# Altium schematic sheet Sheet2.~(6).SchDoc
size A4
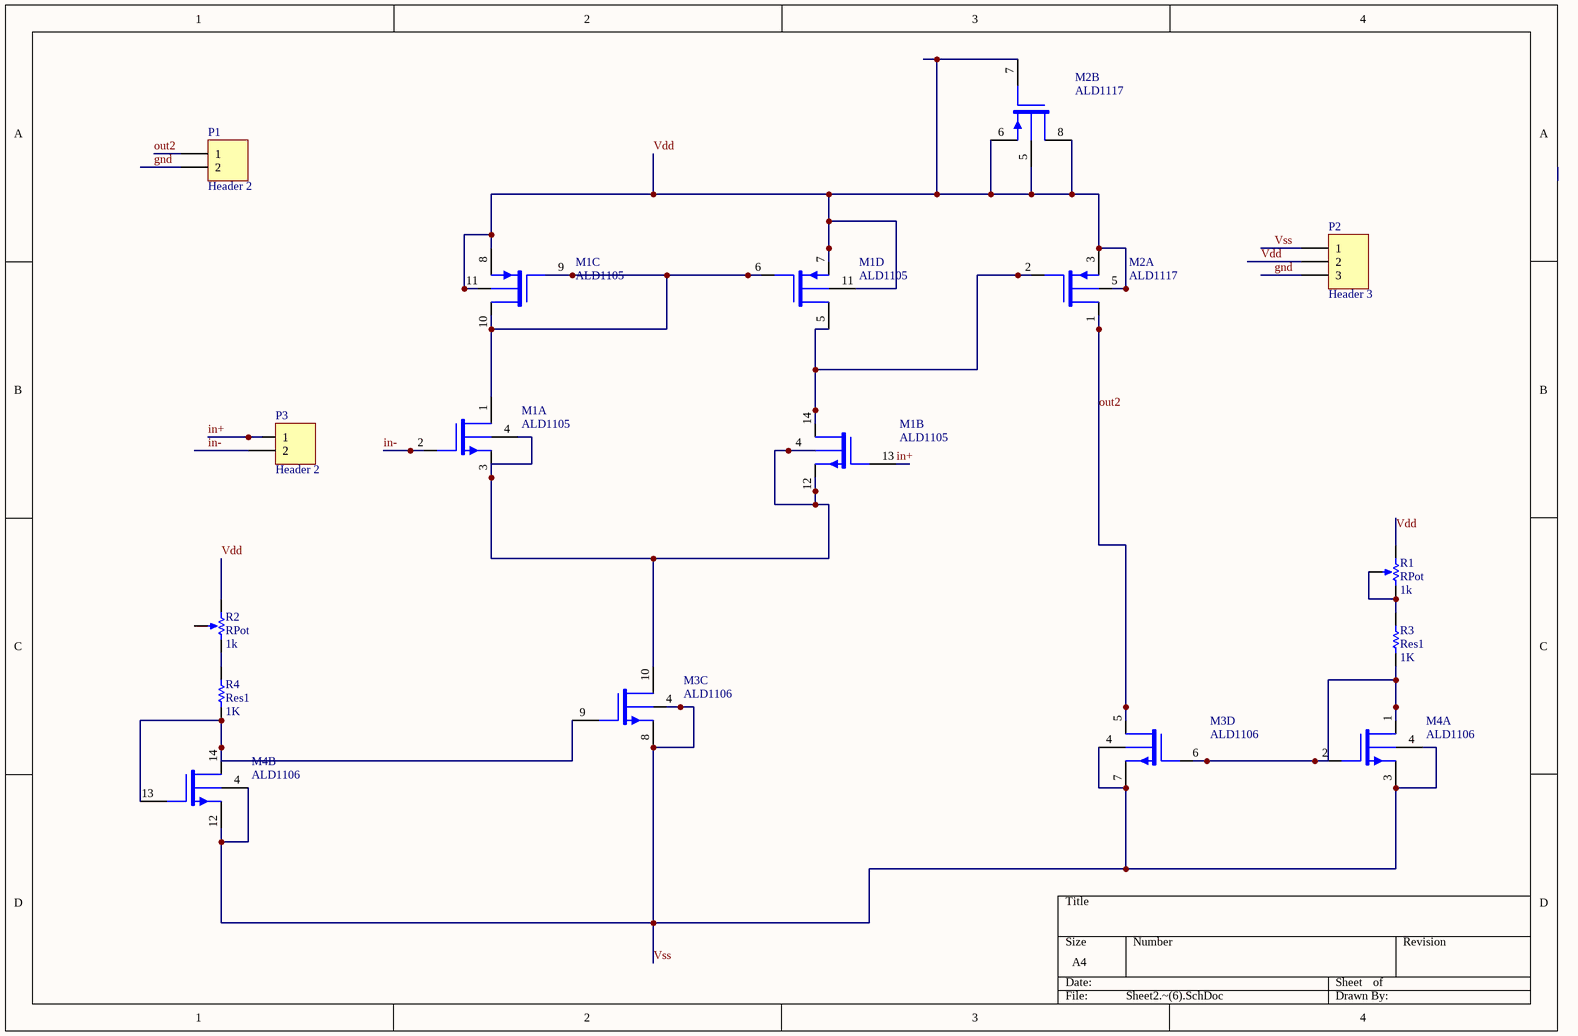
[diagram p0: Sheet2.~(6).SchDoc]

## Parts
M1  ALD1105  [DIP-14]  (parts A,B,C,D of 4)
M2  ALD1117  [DIP-8]  (parts A,B of 2)
M3  ALD1106  [DIP-14]  (parts C,D of 4)
M4  ALD1106  [DIP-14]  (parts A,B of 4)
P1  Header 2  [HDR1X2]
P2  Header 3  [HDR1X3]
P3  Header 2  [HDR1X2]
R1  RPot  value 1k  [VR5]
R2  RPot  value 1k  [VR5]
R3  Res1  value 1K  [AXIAL-0.3]
R4  Res1  value 1K  [AXIAL-0.3]

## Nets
gnd: P1.2 P2.3
in+: M1.13(GN2) P3.1
in-: M1.2(GN1) P3.2
out2: M2.1(DP1) M3.5(DN4) P1.1
Vdd: M1.7(SP1) M1.8(SP2) M1.11(V+) M2.3(SP1) M2.5(V+) M2.6(SP2) M2.7(GP2) M2.8(DP2) P2.2 R1.1(TOP) R2.1(TOP)
Vss: M3.4(V-) M3.7(SN4) M3.8(SN3) M4.3(SN1) M4.4(V-) M4.12(SN2) P2.1
NetM1_1: M1.1(DN1) M1.6(GP1) M1.9(GP2) M1.10(DP2)
NetM1_3: M1.3(SN1) M1.4(V-) M1.12(SN2) M3.10(DN3)
NetM1_5: M1.5(DP1) M1.14(DN2) M2.2(GP1)
NetM3_6: M3.6(GN4) M4.1(DN1) M4.2(GN1) R3.2
NetM3_9: M3.9(GN3) M4.13(GN2) M4.14(DN2) R4.2
NetR1_2: R1.2(TAP) R1.3(BOT) R3.1
NetR2_3: R2.3(BOT) R4.1

Not connected (* = marked no-connect by the designer): R2 2(TAP)

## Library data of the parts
M1 = ALD1105: Dual P-channel and dual N-channel matched MOSFET array
M2 = ALD1117: Dual P-channel matched MOSFET array
M3 M4 = ALD1106: Quad N-channel matched MOSFET array
P1 P3 = Header 2: Header, 2-Pin
P2 = Header 3: Header, 3-Pin
R1 R2 = RPot: Potentiometer; Sim Note: Enter the Resistance value and the set point into parameter fields.; Set Position: 0.5
R3 R4 = Res1: Resistor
